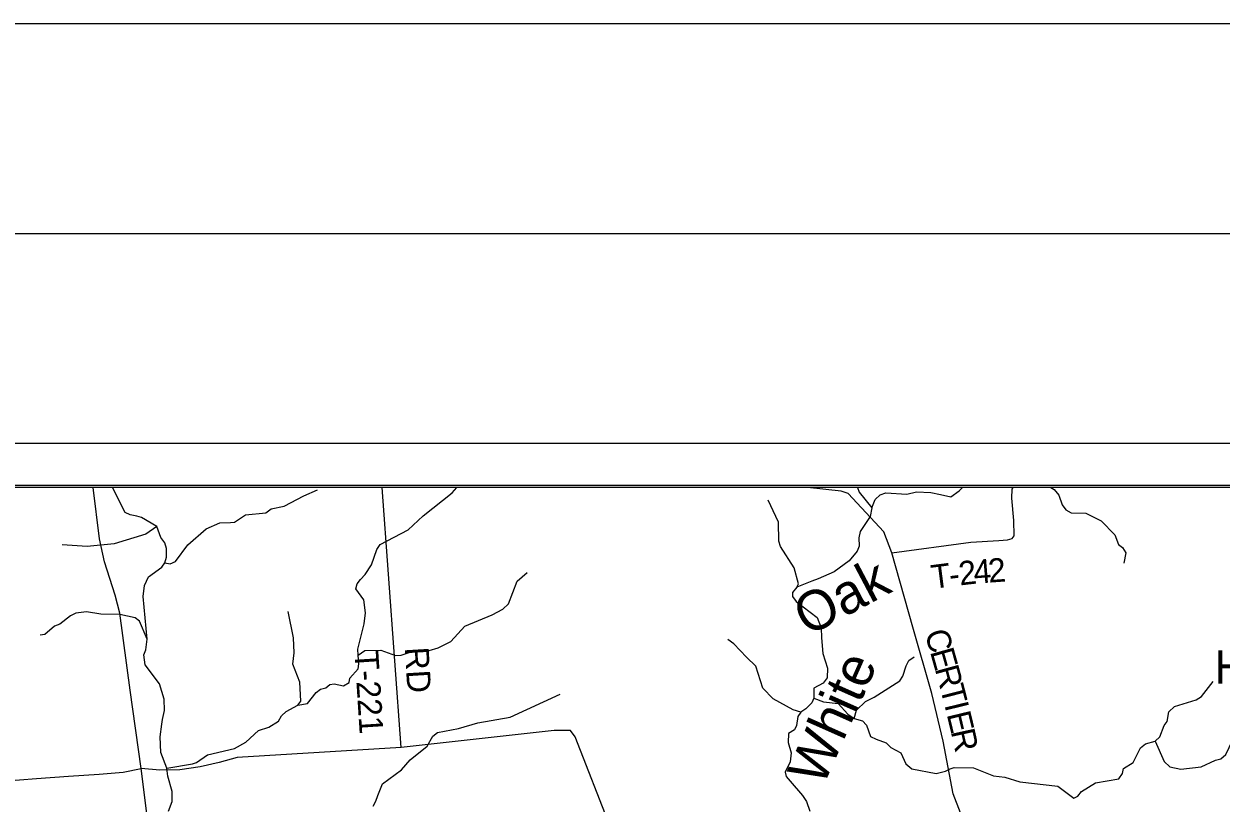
# Model space of a CAD drawing. Extents: x 0 to 34, y 0 to 22.
# Drawn here: x 3.465 to 6.32, y 20.142 to 22 of the extents above; entities that cross this region are included whole.
import ezdxf

# ---------------------------------------------------------------- set-up
doc = ezdxf.new("R2010")
doc.units = 0
for name, color, linetype in [('Default', 7, 'Continuous'), ('GM_X_County_Road', 7, 'Continuous'), ('GM_X_County_Road_Text', 7, 'Continuous'), ('GM_X_Minor_River', 7, 'Continuous'), ('GM_X_Minor_River_Text', 7, 'Continuous'), ('GM_X_State_Route', 7, 'Continuous'), ('GM_X_Township_Road', 7, 'Continuous'), ('GM_X_Township_Road_Text', 7, 'Continuous'), ('GM_X_Unincorporated_Text', 7, 'Continuous'), ('SH_Border', 7, 'Continuous'), ('SH_Cut_Line', 7, 'Continuous'), ('SH_Data', 7, 'Continuous')]:
    doc.layers.add(name, color=color, linetype=linetype)

msp = doc.modelspace()

# ---------------------------------------------------------------- linework, layer by layer
at = {"layer": 'Default'}
msp.add_lwpolyline([(6.7802, 17.4233), (6.9652, 18.9204), (7.0779, 19.8324), (7.1423, 20.3535), (7.155, 20.4756), (7.1718, 20.7748), (7.1725, 20.7885), (6.8666, 20.8494), (6.6419, 20.8941), (2.4006, 20.8941), (2.3791, 20.1601), (2.3212, 18.6531), (2.2797, 17.8302)], dxfattribs=at)
at = {"layer": 'GM_X_County_Road'}
msp.add_lwpolyline([(5.8078, 19.4902), (5.7818, 19.7334), (5.7792, 19.7638), (5.7747, 19.7893), (5.7622, 19.8116), (5.7427, 19.8449), (5.7343, 19.866), (5.7346, 19.9081), (5.731, 20.0244), (5.6988, 20.118), (5.681, 20.1639), (5.6577, 20.2896), (5.6304, 20.4028), (5.5849, 20.5608), (5.5348, 20.7388), (5.516, 20.7887), (5.4308, 20.8798), (5.4141, 20.8852), (5.3337, 20.8941)], dxfattribs=at)
at = {"layer": 'GM_X_Minor_River'}
for points in [[(3.8097, 20.1223), (3.8185, 20.1457), (3.8185, 20.1692), (3.8074, 20.2054), (3.8055, 20.2252), (3.7913, 20.2623), (3.7897, 20.2995), (3.7932, 20.3301), (3.7953, 20.3411), (3.8002, 20.3623), (3.7992, 20.3896), (3.7881, 20.4262), (3.7536, 20.4716), (3.7509, 20.4948), (3.755, 20.5072), (3.7584, 20.5322), (3.7492, 20.6344), (3.7523, 20.6602), (3.7618, 20.6809), (3.7933, 20.7039), (3.8003, 20.7144), (3.8043, 20.728), (3.8043, 20.7488), (3.8007, 20.7625), (3.7911, 20.7748), (3.7817, 20.8012), (3.7449, 20.8227), (3.7339, 20.8259), (3.7181, 20.8292), (3.7064, 20.8347), (3.6759, 20.8941)], [(3.8003, 20.7144), (3.8135, 20.7126), (3.8261, 20.7181), (3.8556, 20.7574), (3.8995, 20.7954), (3.932, 20.8104), (3.9571, 20.8107), (3.9666, 20.8117), (3.9934, 20.829), (4.0417, 20.8339), (4.0544, 20.8435), (4.0856, 20.8495), (4.1323, 20.8741), (4.1651, 20.8887)], [(3.8055, 20.2252), (3.8667, 20.2355), (3.8762, 20.2384), (3.9027, 20.2569), (3.9667, 20.2718), (3.9939, 20.2865), (4.0243, 20.3144), (4.0484, 20.3227), (4.0718, 20.3367), (4.0792, 20.3499), (4.09, 20.3599), (4.1179, 20.375), (4.1411, 20.3788), (4.1617, 20.405), (4.1717, 20.4132), (4.1846, 20.4164), (4.1946, 20.4245), (4.2042, 20.4259), (4.2265, 20.4213), (4.2402, 20.4294), (4.2423, 20.4397), (4.262, 20.4617), (4.2638, 20.4738), (4.2615, 20.494), (4.261, 20.5084), (4.276, 20.5688), (4.2792, 20.5957), (4.2755, 20.6265), (4.2562, 20.6526), (4.2595, 20.6647), (4.2676, 20.6745), (4.2785, 20.6868), (4.2933, 20.7097), (4.3064, 20.7463), (4.3146, 20.7583), (4.3812, 20.7932), (4.4167, 20.8267), (4.4859, 20.8817), (4.4973, 20.8941)], [(5.4532, 20.8941), (5.4569, 20.8829), (5.4874, 20.8456), (5.4829, 20.8255), (5.4591, 20.7891), (5.4562, 20.7744), (5.457, 20.7543), (5.4522, 20.7422), (5.4329, 20.7194), (5.3975, 20.6934), (5.3589, 20.6766), (5.3444, 20.6708), (5.3085, 20.6566), (5.298, 20.6439), (5.2979, 20.6344), (5.3071, 20.6225), (5.3569, 20.5841), (5.366, 20.5593), (5.3671, 20.5354), (5.3702, 20.4981), (5.3818, 20.463), (5.3806, 20.4403), (5.3713, 20.4279), (5.3491, 20.4158), (5.349, 20.3915), (5.3443, 20.3806), (5.3296, 20.3664), (5.3177, 20.3583), (5.3107, 20.3478), (5.3073, 20.3262), (5.3026, 20.316), (5.2888, 20.3072), (5.2873, 20.2859), (5.2948, 20.2615), (5.2926, 20.24), (5.2804, 20.2155), (5.2829, 20.2048), (5.2921, 20.1937), (5.3219, 20.1594), (5.3311, 20.1452), (5.3391, 20.1223)], [(5.4874, 20.8456), (5.4953, 20.8659), (5.5069, 20.8771), (5.5206, 20.8814), (5.5706, 20.8783), (5.5935, 20.8836), (5.6276, 20.8822), (5.651, 20.8777), (5.6756, 20.8723), (5.6952, 20.886), (5.7036, 20.8941)], [(5.9142, 20.8941), (5.9221, 20.8893), (5.9332, 20.8762), (5.9415, 20.853), (5.9497, 20.8407), (5.9624, 20.8336), (5.9981, 20.833), (6.0342, 20.8149), (6.067, 20.781), (6.0753, 20.7581), (6.085, 20.7515), (6.0928, 20.7388), (6.0882, 20.7135)], [(5.3085, 20.6566), (5.312, 20.6645), (5.3021, 20.7027), (5.2692, 20.7537), (5.2653, 20.7666), (5.2649, 20.8118), (5.2583, 20.8252), (5.24, 20.8638)], [(3.7817, 20.8012), (3.7556, 20.7827), (3.6801, 20.7601), (3.6155, 20.7536), (3.5556, 20.7573)], [(4.2615, 20.494), (4.278, 20.5054), (4.3159, 20.5059), (4.351, 20.4936), (4.3646, 20.4945), (4.3879, 20.5024), (4.4312, 20.5055), (4.4526, 20.5115), (4.4832, 20.527), (4.5164, 20.5636), (4.5817, 20.5902), (4.607, 20.6041), (4.6201, 20.6168), (4.6408, 20.6707), (4.665, 20.6915)], [(3.7584, 20.5322), (3.7406, 20.5754), (3.7297, 20.5835), (3.6931, 20.591), (3.6476, 20.5918), (3.6139, 20.5977), (3.5881, 20.5943), (3.5754, 20.5885), (3.5504, 20.568), (3.5378, 20.5633), (3.5147, 20.5436), (3.503, 20.5423)], [(4.1179, 20.375), (4.1249, 20.3844), (4.1223, 20.4303), (4.1056, 20.4731), (4.1095, 20.5), (4.1078, 20.5357), (4.0949, 20.5985)], [(5.3177, 20.3583), (5.2996, 20.3639), (5.2519, 20.3901), (5.2273, 20.416), (5.2108, 20.4678), (5.1884, 20.4895), (5.1578, 20.5215), (5.144, 20.5316)], [(5.4453, 20.3436), (5.4506, 20.3628), (5.4718, 20.3841), (5.4925, 20.394), (5.5542, 20.4335), (5.5608, 20.4444), (5.5689, 20.4689), (5.5755, 20.4813), (5.5886, 20.4906)], [(5.349, 20.3915), (5.3717, 20.3832), (5.4069, 20.3788), (5.4299, 20.3537), (5.4453, 20.3436), (5.4653, 20.3375), (5.4742, 20.3275), (5.484, 20.3004), (5.4972, 20.2941), (5.5217, 20.285), (5.5329, 20.2738), (5.5565, 20.2612), (5.5686, 20.2352), (5.5824, 20.2236), (5.641, 20.2124), (5.6631, 20.2177), (5.6738, 20.2232), (5.6834, 20.2264), (5.7296, 20.2253), (5.7771, 20.2062), (5.8047, 20.2035), (5.8402, 20.1926), (5.9307, 20.1816), (5.9689, 20.1536), (5.9788, 20.158), (5.9877, 20.1692), (6.0211, 20.1895), (6.0766, 20.1996), (6.0852, 20.2123), (6.0877, 20.2244), (6.1103, 20.2381), (6.1283, 20.273), (6.1399, 20.2831), (6.1628, 20.2891), (6.1743, 20.2999), (6.1843, 20.3263), (6.1916, 20.3361), (6.1954, 20.3588), (6.2089, 20.3722), (6.2608, 20.3876), (6.2738, 20.3954), (6.3014, 20.4313)], [(4.2973, 20.1341), (4.3036, 20.1465), (4.3088, 20.1593), (4.3195, 20.1872), (4.3652, 20.2209), (4.3861, 20.2445), (4.4261, 20.2772), (4.4402, 20.3008), (4.451, 20.3097), (4.5008, 20.3195), (4.5477, 20.3327), (4.6242, 20.3462), (4.7439, 20.4015)], [(6.1628, 20.2891), (6.1843, 20.2406), (6.1985, 20.2278), (6.2242, 20.2221), (6.2732, 20.2284), (6.3069, 20.2438), (6.3198, 20.2474), (6.3317, 20.2574), (6.3479, 20.2909), (6.3669, 20.3137), (6.3783, 20.3199), (6.4184, 20.3318)]]:
    msp.add_lwpolyline(points, dxfattribs=at)
at = {"layer": 'GM_X_State_Route'}
for points in [[(3.762, 20.0852), (3.7441, 20.2242), (3.7179, 20.4105), (3.6929, 20.5947), (3.6822, 20.6372), (3.6571, 20.7171), (3.6447, 20.772), (3.6293, 20.8941)], [(2.9228, 20.1585), (3.0082, 20.1632), (3.0935, 20.1705), (3.1668, 20.1769), (3.2472, 20.1824), (3.3269, 20.1872), (3.4134, 20.1937), (3.4946, 20.2), (3.5709, 20.2056), (3.6438, 20.2104), (3.7014, 20.2155), (3.7441, 20.2242)]]:
    msp.add_lwpolyline(points, dxfattribs=at)
at = {"layer": 'GM_X_Township_Road'}
msp.add_line((4.3645, 20.2742), (4.3191, 20.8941), dxfattribs=at)
for points in [[(5.5348, 20.7388), (5.7233, 20.7635), (5.7903, 20.7676), (5.8108, 20.7695), (5.8222, 20.7724), (5.8269, 20.7787), (5.826, 20.8152), (5.8209, 20.8689), (5.822, 20.8901), (5.8242, 20.8941)], [(4.8738, 18.862), (4.8629, 19.5178), (4.8567, 19.7096), (4.825, 19.7664), (4.725, 19.8931), (4.7788, 19.9289), (4.8156, 19.9458), (4.8475, 19.9642), (4.8648, 19.9768), (4.8716, 19.9964), (4.8737, 20.0298), (4.8643, 20.0816), (4.7796, 20.2995), (4.7681, 20.3149), (4.7293, 20.3148), (4.3645, 20.2742), (3.973, 20.2502), (3.9306, 20.2384), (3.8852, 20.2282), (3.8365, 20.2207), (3.789, 20.22), (3.7441, 20.2242)]]:
    msp.add_lwpolyline(points, dxfattribs=at)
at = {"layer": 'SH_Border'}
msp.add_lwpolyline([(1.5, 21.5), (33.5, 21.5), (33.5, 0.5), (1.5, 0.5)], close=True, dxfattribs=at)
at = {"layer": 'SH_Cut_Line'}
msp.add_lwpolyline([(0, 0), (34, 0), (34, 22), (0, 22)], close=True, dxfattribs=at)
msp.add_lwpolyline([(8.9, 14.2922), (8.9, 20.8941), (2.4006, 20.8941), (2.3791, 20.1601), (2.3212, 18.6531), (2.2797, 17.8302)], dxfattribs=at)
at = {"layer": 'SH_Data'}
for p, q in [((2, 21), (9, 21)), ((2.1, 20.9), (8.9, 20.9))]:
    msp.add_line(p, q, dxfattribs=at)

# ---------------------------------------------------------------- texts
at = {"layer": 'GM_X_County_Road_Text'}
for s, rotation, p in [('C', 285.7186, (5.613, 20.5478)), ('E', 285.7161, (5.6256, 20.5029)), ('R', 285.4165, (5.6371, 20.4621)), ('T', 284.4073, (5.6494, 20.4173)), ('I', 283.6879, (5.66, 20.3763)), ('E', 283.5789, (5.6655, 20.3537)), ('R', 282.5045, (5.6754, 20.3127))]:
    msp.add_text(s, height=0.0568, rotation=rotation, dxfattribs=at).set_placement(p)
at = {"layer": 'GM_X_Minor_River_Text'}
for s, rotation, p in [('Oak', 27.8617, (5.3338, 20.5381)), ('White', 66.0629, (5.3703, 20.1781))]:
    msp.add_text(s, height=0.09471, rotation=rotation, dxfattribs=at).set_placement(p)
at = {"layer": 'GM_X_Township_Road_Text'}
for s, height, rotation, p in [('T', 0.0568, 7.3313, (5.6324, 20.6523)), ('2', 0.0568, 6.5557, (5.6975, 20.6606)), ('4', 0.0568, 4.5322, (5.7317, 20.6645)), ('2', 0.0568, 4.0521, (5.7665, 20.6673)), ('-', 0.0568, 7.1691, (5.6745, 20.6577)), ('T-221', 0.05682, 273.6462, (4.253, 20.503)), ('RD', 0.05682, 273.4534, (4.373, 20.5122))]:
    msp.add_text(s, height=height, rotation=rotation, dxfattribs=at).set_placement(p)
at = {"layer": 'GM_X_Unincorporated_Text'}
msp.add_text('Hollowtown', height=0.07898, rotation=0, dxfattribs=at).set_placement((6.3048, 20.4267))

doc.saveas('drawing.dxf')
